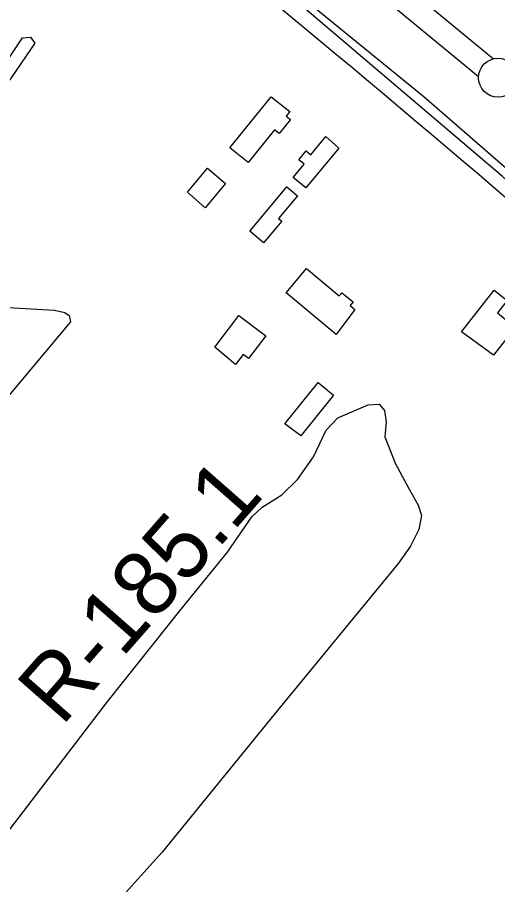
# Model space of a CAD drawing. Extents: x 3355724 to 3393621, y 594744 to 620174.
# Drawn here: x 3374114 to 3374730, y 615086 to 616199 of the extents above; entities that cross this region are included whole.
import ezdxf

# ---------------------------------------------------------------- set-up
doc = ezdxf.new("R2010")
doc.units = 0
for name, color, linetype in [('V-BLDG-OTLN', 7, 'Continuous'), ('V-LEVE-TOET', 7, 'Continuous'), ('V-RIVR-RANG-IDEN', 7, 'Continuous'), ('V-ROAD-CNTR', 7, 'Continuous'), ('V-SITE-VEGE', 7, 'Continuous'), ('V-SURV-LINE', 7, 'Continuous'), ('V-TOPO-SHOR', 7, 'Continuous')]:
    doc.layers.add(name, color=color, linetype=linetype)

msp = doc.modelspace()

# ---------------------------------------------------------------- linework, layer by layer
at = {"layer": 'V-BLDG-OTLN'}
for points in [[(3374387.015, 616031.284), (3374439.9390000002, 616096.886), (3374463.719, 616077.7000000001), (3374459.182, 616072.076), (3374464.593, 616067.712), (3374450.083, 616049.727), (3374444.3340000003, 616054.363), (3374410.3910000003, 616012.287)], [(3374526.938, 616030.916), (3374484.321, 615979.81), (3374468.1240000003, 615993.318), (3374482.327, 616010.35), (3374475.511, 616016.033), (3374484.9560000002, 616027.36), (3374490.807, 616022.482), (3374510.093, 616045.61)], [(3374332.6920000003, 615974.639), (3374358.126, 616005.025), (3374381.403, 615985.54), (3374355.154, 615954.177)], [(3374412.762, 615924.504), (3374460.194, 615981.135), (3374473.844, 615969.701), (3374449.497, 615940.634), (3374453.505, 615937.277), (3374430.215, 615909.471)], [(3374523.35, 615791.726), (3374459.125, 615845.3420000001), (3374485.1410000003, 615876.507), (3374527.309, 615841.304), (3374530.7600000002, 615845.436), (3374544.918, 615833.617), (3374541.108, 615829.055), (3374547.125, 615824.031)], [(3374683.944, 615795.539), (3374725.869, 615848.711), (3374742.861, 615835.313), (3374730.401, 615819.511), (3374740.219, 615811.769), (3374752.575, 615827.439), (3374765.8310000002, 615816.986), (3374725, 615765.2000000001)], [(3374367.61, 615775.5160000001), (3374398.535, 615816.255), (3374433.003, 615790.089), (3374410.86, 615760.92), (3374403.96, 615766.156), (3374394.345, 615753.492)], [(3374457.441, 615677.154), (3374500.056, 615730.327), (3374520.045, 615714.307), (3374478.063, 615661.9230000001)]]:
    msp.add_lwpolyline(points, close=True, dxfattribs=at)
at = {"layer": 'V-LEVE-TOET'}
msp.add_lwpolyline([(3375825.827, 615008.099), (3375822.0300000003, 615015.069), (3375811.421, 615025.452), (3375795.215, 615044.861), (3375673.98, 615158.795), (3375432.599, 615386.572), (3375213.561, 615584.466), (3374890.5870000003, 615875.407), (3374635.994, 616096.192), (3374322.151, 616352.343), (3373944.17, 616649.422), (3373708.889, 616836.304), (3373573.176, 616934.682), (3373207.762, 617215.082), (3372868.8510000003, 617474.657), (3372670.815, 617620.3910000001), (3372460.949, 617765.402), (3372217.63, 617927.042), (3371905.281, 618137.949), (3371607.651, 618305.732), (3371539.629639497, 618342.7830789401)], dxfattribs=at)
at = {"layer": 'V-ROAD-CNTR'}
msp.add_arc((3363183.3422084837, 602512.5921495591), 17736.984324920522, 47.255929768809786, 52.738199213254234, dxfattribs=at)
at = {"layer": 'V-SITE-VEGE'}
for points in [[(3374081.039, 616113.2390000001), (3374120.719, 616172.367), (3374131.015, 616173.076), (3374136.524, 616165.537), (3374035.951, 616018.402)], [(3374102.29, 615826.341), (3374162.021, 615823.046), (3374175.069, 615820.328), (3374180.5700000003, 615816.224), (3374182.651, 615807.991), (3374021.7660000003, 615616.781)], [(3374066.179, 615107.52), (3374229.073, 615320.014), (3374326.275, 615441.741), (3374383.775, 615512.579), (3374415.251, 615557.959), (3374428.2660000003, 615570.345), (3374453.628, 615586.192), (3374473.492, 615606.1460000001), (3374494.019, 615635.025), (3374510.415, 615669.386), (3374525.482, 615685.209), (3374564.572, 615701.775), (3374578.3000000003, 615702.492), (3374585.183, 615694.269), (3374587.276, 615679.86), (3374585.947, 615660.635), (3374599.069, 615627.028), (3374616.9930000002, 615593.43), (3374628.7090000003, 615572.8640000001), (3374632.859, 615559.831), (3374629.469, 615541.974), (3374618.5330000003, 615520.669), (3374603.48, 615498.667), (3374443.9760000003, 615304.715), (3374300.221, 615127.963), (3374241.332, 615063.299)]]:
    msp.add_lwpolyline(points, dxfattribs=at)
at = {"layer": 'V-SURV-LINE'}
for points in [[(3374298.2171917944, 616497.0781073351), (3374725.087066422, 616145.4922372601)], [(3374706.0186143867, 616122.3320523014), (3374279.14930784, 616473.917454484)]]:
    msp.add_lwpolyline(points, dxfattribs=at)
msp.add_circle((3374730.96979, 616121.2137899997), 25, dxfattribs=at)
at = {"layer": 'V-TOPO-SHOR'}
msp.add_lwpolyline([(3375787.411, 615027.406), (3375610.893, 615199.671), (3375326.404, 615471.1460000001), (3375029.511, 615730.1630000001), (3374736.75, 615994.711), (3374423.2600000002, 616261.287), (3374143.719, 616483.735), (3373867.642, 616700.667), (3373729.957, 616805.334)], dxfattribs=at)

# ---------------------------------------------------------------- texts
at = {"layer": 'V-RIVR-RANG-IDEN'}
msp.add_text('R-185.1', height=82.99999799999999, rotation=48.70283707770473, dxfattribs=at).set_placement((3374171.274, 615288.305))

doc.saveas('drawing.dxf')
